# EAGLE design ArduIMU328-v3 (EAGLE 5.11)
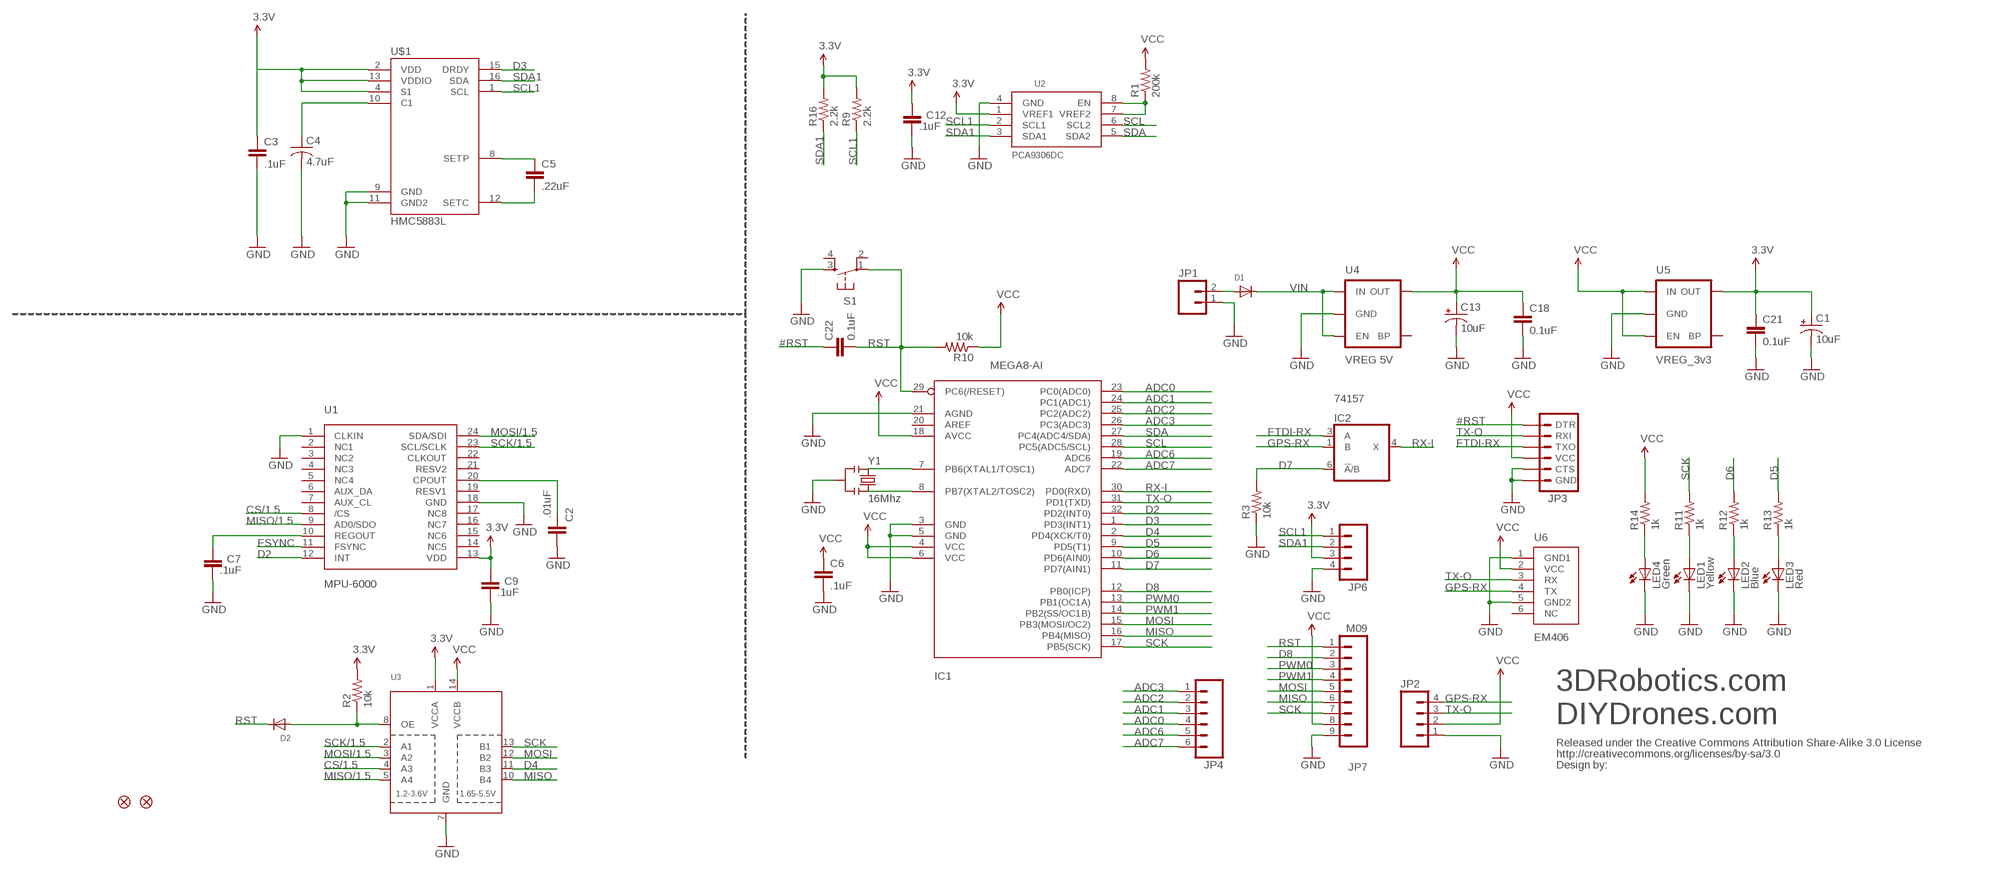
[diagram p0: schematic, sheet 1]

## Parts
C1  10uF  CAP_POL1206  [EIA3216]
C2  .01uF  C-EUC0402  [C0402]
C3  .1uF  CAP0402-CAP  [0402-CAP]
C4  4.7uF  C-USC1206  [C1206]
C5  .22uF  CAP0402-CAP  [0402-CAP]
C6  .1uF  CAP0402-CAP  [0402-CAP]
C7  .1uF  C-EUC0402  [C0402]
C9  .1uF  C-EUC0402  [C0402]
C12  .1uF  C-EUC0402  [C0402]
C13  10uF  CAP_POL1206  [EIA3216]
C18  0.1uF  CAP0402-CAP  [0402-CAP]
C21  0.1uF  CAP0402-CAP  [0402-CAP]
C22  0.1uF  CAP0402-CAP  [0402-CAP]
D1  DIODESOD-123  [SOD-123]
D2  DIODESOD-123  [SOD-123]
IC1  MEGA8-AI  [TQFP32-08]
IC2  74157  741G3157DBVR  [DBV_R-PDSO-G6]
JP1  M02PTH  [1X02]
JP2  M04PTH  [1X04]
JP3  ARDUINO_SERIAL_PROGRAMPTH  [1X06]
JP4  M06SIP  [1X06]
JP5  FIDUCIAL1X2  [FIDUCIAL-1X2]
JP6  M04PTH  [1X04]
JP7  M09  [1X09]
JP8  FIDUCIAL1X2  [FIDUCIAL-1X2]
LED1  Yellow  LED0603  [LED-0603]
LED2  Blue  LED0603  [LED-0603]
LED3  Red  LED0603  [LED-0603]
LED4  Green  LED0603  [LED-0603]
R1  200k  RESISTOR0402  [C0402]
R2  10k  RESISTOR0402-RES  [0402-RES]
R3  10k  RESISTOR0402-RES  [0402-RES]
R9  2.2k  RESISTOR0402  [C0402]
R10  10k  RESISTOR0402-RES  [0402-RES]
R11  1k  RESISTOR0402-RES  [0402-RES]
R12  1k  RESISTOR0402-RES  [0402-RES]
R13  1k  RESISTOR0402-RES  [0402-RES]
R14  1k  RESISTOR0402-RES  [0402-RES]
R16  2.2k  RESISTOR0402  [C0402]
S1  TAC_SWITCHSMD  [TACTILE_SWITCH_SMD]
U1  MPU-6000  MPU-3000  [QFN-24]
U2  PCA9306DC  [VSSOP8]
U3  TXB0104PWR  [TSSOP14]
U4  VREG 5V  V_REG_LDOSMD  [SOT23-5]
U5  VREG_3v3  V_REG_LDOSMD  [SOT23-5]
U6  EM406  [EM406]
U$1  HMC5883L  [LPCC16]
U$2  CREATIVE_COMMONS  [CREATIVE_COMMONS]
Y1  16Mhz  RESONATORSMD  [RESONATOR-SMD]

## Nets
3.3V: C1.A(+) C3.1 C9.2 C12.2 C21.1 JP6.3 R2.2 R9.2 R16.2 U1.13(VDD) U2.1(VREF1) U3.1(VCCA) U5.5(OUT) U$1.2(VDD) U$1.4(S1) U$1.13(VDDIO)
#RST: C22.1 JP3.1(DTR)
ADC0: IC1.23(PC0(ADC0)) JP4.4
ADC1: IC1.24(PC1(ADC1)) JP4.3
ADC2: IC1.25(PC2(ADC2)) JP4.2
ADC3: IC1.26(PC3(ADC3)) JP4.1
ADC6: IC1.19(ADC6) JP4.5
ADC7: IC1.22(ADC7) JP4.6
CS/1.5: U1.8(/CS) U3.4(A3)
D2: IC1.32(PD2(INT0)) U1.12(INT)
D3: IC1.1(PD3(INT1)) U$1.15(DRDY)
D4: IC1.2(PD4(XCK/T0)) U3.11(B3)
D5: IC1.9(PD5(T1)) R13.2
D6: IC1.10(PD6(AIN0)) R12.2
D7: IC1.11(PD7(AIN1)) IC2.6(!A!/B) R3.2
D8: IC1.12(PB0(ICP)) JP7.2
FSYNC: U1.11(FSYNC)
FTDI-RX: IC2.3(A) JP3.3(TXO)
GND: C1.C(-) C2.1 C3.2 C4.2 C6.2 C7.1 C9.1 C12.1 C13.C(-) C18.2 C21.2 IC1.3(GND) IC1.5(GND) IC1.21(AGND) JP1.1 JP2.1 JP3.5(CTS) JP3.6(GND) JP6.4 JP7.9 LED1.C LED2.C LED3.C LED4.C R3.1 S1.3 U1.1(CLKIN) U1.18(GND) U2.4(GND) U3.7(GND) U4.2(GND) U5.2(GND) U6.1(GND1) U6.5(GND2) U$1.9(GND) U$1.11(GND2) Y1.2
GPS-RX: IC2.1(B) JP2.4 U6.4(TX)
MISO: IC1.16(PB4(MISO)) JP7.6 U3.10(B4)
MISO/1.5: U1.9(AD0/SDO) U3.5(A4)
MOSI: IC1.15(PB3(MOSI/OC2)) JP7.5 U3.12(B2)
MOSI/1.5: U1.24(SDA/SDI) U3.3(A2)
N$1: R1.1 U2.7(VREF2) U2.8(EN)
N$2: C2.2 U1.20(CPOUT)
N$3: C7.2 U1.10(REGOUT)
N$4: C4.1 U$1.10(C1)
N$5: IC1.7(PB6(XTAL1/TOSC1)) Y1.1
N$6: C5.1 U$1.8(SETP)
N$7: IC1.8(PB7(XTAL2/TOSC2)) Y1.3
N$8: C5.2 U$1.12(SETC)
N$9: D2.A R2.1 U3.8(OE)
N$11: LED1.A R11.1
N$12: LED2.A R12.1
N$13: LED3.A R13.1
N$14: D1.A JP1.2
N$17: LED4.A R14.1
PWM0: IC1.13(PB1(OC1A)) JP7.3
PWM1: IC1.14(PB2(SS/OC1B)) JP7.4
RST: C22.2 D2.C IC1.29(PC6(/RESET)) JP7.1 R10.2 S1.1
RX-I: IC1.30(PD0(RXD)) IC2.4(X)
SCK: IC1.17(PB5(SCK)) JP7.7 R11.2 U3.13(B1)
SCK/1.5: U1.23(SCL/SCLK) U3.2(A1)
SCL: IC1.28(PC5(ADC5/SCL)) U2.6(SCL2)
SCL1: JP6.1 R9.1 U2.2(SCL1) U$1.1(SCL)
SDA: IC1.27(PC4(ADC4/SDA)) U2.5(SDA2)
SDA1: JP6.2 R16.1 U2.3(SDA1) U$1.16(SDA)
TX-O: IC1.31(PD1(TXD)) JP2.3 JP3.2(RXI) U6.3(RX)
VCC: C6.1 C13.A(+) C18.1 IC1.4(VCC) IC1.6(VCC) IC1.18(AVCC) JP2.2 JP3.4(VCC) JP7.8 R1.2 R10.1 R14.2 U3.14(VCCB) U4.5(OUT) U5.1(IN) U5.3(EN) U6.2(VCC)
VIN: D1.C U4.1(IN) U4.3(EN)
Unconnected: IC1.20(AREF) S1.2 S1.4 U1.2(NC1) U1.3(NC2) U1.4(NC3) U1.5(NC4) U1.6(AUX_DA) U1.7(AUX_CL) U1.14(NC5) U1.15(NC6) U1.16(NC7) U1.17(NC8) U1.19(RESV1) U1.21(RESV2) U1.22(CLKOUT) U4.4(BP) U5.4(BP) U6.6(NC)

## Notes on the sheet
- 3DRobotics.com
- DIYDrones.com

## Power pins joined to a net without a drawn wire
GND: IC2.2(GND)
VCC: IC2.5(VCC)

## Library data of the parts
C1 C13 = SparkFun:CAP_POL: Capacitor Polarized
C2 C7 C9 C12 = SmartPrj:C-EU: CAPACITOR, European symbol
C3 C5 C6 C18 C21 C22 = SparkFun:CAP: Capacitor
C4 = rcl:C-US: CAPACITOR, American symbol
D1 D2 = adafruit:DIODE: Diode
IC1 = atmel:MEGA8: MICROCONTROLLER 8 Kbytes FLASH, 1 kbytes SRAM, 512 bytes EEPROM, USART, 6-channel 10 bit ADC, 2-channel 8 bit ADC Pin compatible with Atmega48, ATMega88, ATMega168 Source: avr.lbr
IC2 = 74xx-little-de:74*1G3157: Single-Pole, Double-Throw Analog Switch Source: http://focus.ti.com/lit/ds/symlink/sn74lvc1g3157.pdf
JP1 = SparkFun:M02: Header 2
JP2 JP6 = SparkFun:M04: Header 4 Standard 4-pin 0.1" header. Use with straight break away headers (SKU : PRT-00116), right angle break away headers (PRT-00553), swiss pins (PRT-00743), machine pins (PRT-00117), and female headers (PRT-00115). Molex polarized connector foot print use with SKU : PRT-08231 with associated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
JP3 = SparkFun:ARDUINO_SERIAL_PROGRAM
JP4 = SparkFun:M06: Header 6 Standard 6-pin 0.1" header. Use with straight break away headers (SKU : PRT-00116), right angle break away headers (PRT-00553), swiss pins (PRT-00743), machine pins (PRT-00117), and female headers (PRT-00115). Molex polarized connector foot print use with SKU : PRT-08094 with associated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
JP5 JP8 = SparkFun:FIDUCIAL: Fiducial Alignment Points
JP7 = SparkFun:M09: Header 9 Standard 9-pin 0.1" header. Use with straight break away headers (SKU : PRT-00116), right angle break away headers (PRT-00553), swiss pins (PRT-00743), machine pins (PRT-00117), and female headers (PRT-00115).
LED1-LED4 = DIYdrones3:LED: LEDs
R1 R9 R16 = DIYdrones3:RESISTOR: Resistor
R2 R3 R10-R14 = SparkFun:RESISTOR: Resistor
S1 = DIYdrones3:TAC_SWITCH: Momentary Switch Button commonly used for reset or general input. Spark Fun Electronics SKU : COM-00097
U1 = 3DRobotics_Master_Library:MPU-3000: Invensense MPU-3000 Motion Processing Unit The MPU-30X0 Motion Processing Unit (MPU?) is the world?s first motion processing solution with integrated 6-axis sensor fusion for smart phone applications. The MPU-30X0 has an embedded 3- axis gyroscope and Digital Motion Processor? (DMP) hardware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; DATASHEET: http://invensense.com/mems/gyro/documents/PS-MPU-3000A-00_v2.6.pdf; LINK: http://www.invensense.com/mems/gyro/mpu3000.html; MFGPN: MPU-3000
U2 = DIYdrones_082610:PCA9306DC
U3 = adafruit:TXB0104PWR: 4-Bit Bi-Directional Level Shifter 1.2V-3.6V (VCCA) to 1.65V-5.5V (VCCB) bi-directional level shifter with auto direction sensing. Max data rate - VCCA 1.8V: 20Mbps (50ns), VCCA 3.3V: 100Mbps (10ns) Digikey: 296-21929-1-ND
U4 U5 = DIYdrones3:V_REG_LDO: Voltage Regulator LDO Standard 150mA LDO voltage regulator in SOT-23 layout. Micrel part MIC5205. BP (by-pass) pin is used to lower output noise with 470pF cap.
U6 = DIYdrones3:EM406: EM406 Connector Proven layout and schematic for EM406 connector. Spark Fun Electronics SKU : GPS-00579
U$1 = 3DRobotics:HMC5883L: Honeywell HMC5883L 3-axis digital compass IC Successor to the HMC5843.; DATASHEET: http://www.dsscircuits.com/images/datasheets/HMC5883L.pdf; LINK: http://parts.digikey.com/1/parts/2057013-ic-compass-3-axis-i2c-16lcc-smd-hmc5883l-tr.html; MFGPN: HMC5883L-TR
U$2 = SparkFun:CREATIVE_COMMONS
Y1 = DIYdrones3:RESONATOR: Resonator Small SMD resonator. This is the itty bitty 10/20MHz resonators with built in caps. CSTCE10M0G55 and CSTCE20M0V53. Footprint has been reviewed closely but hasn't been tested yet.

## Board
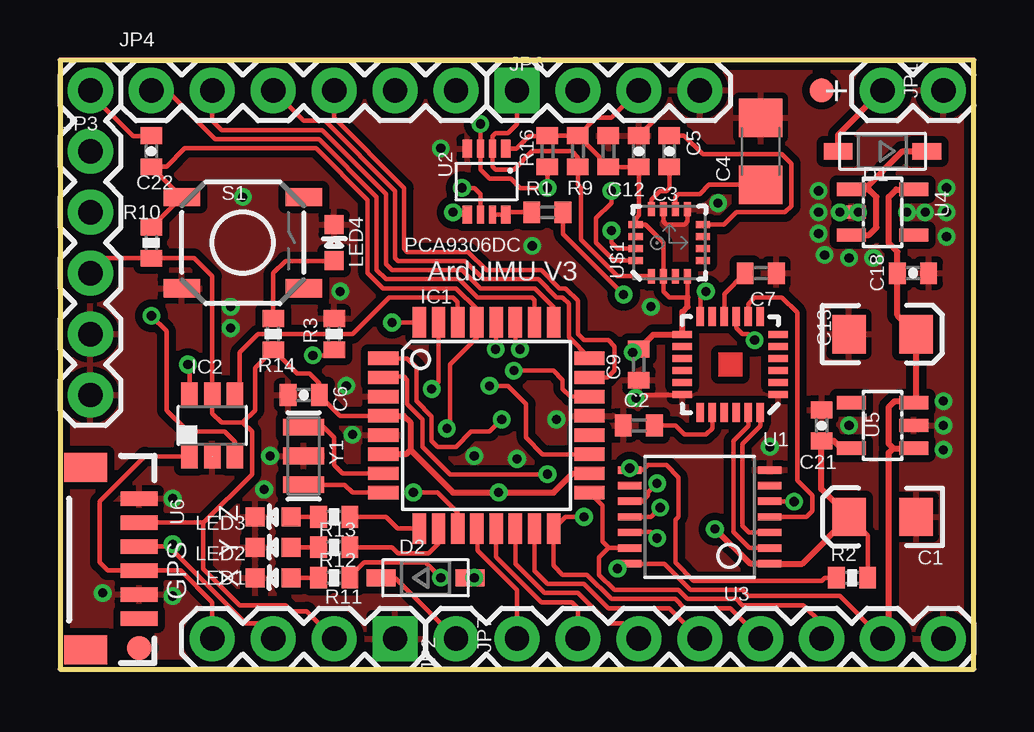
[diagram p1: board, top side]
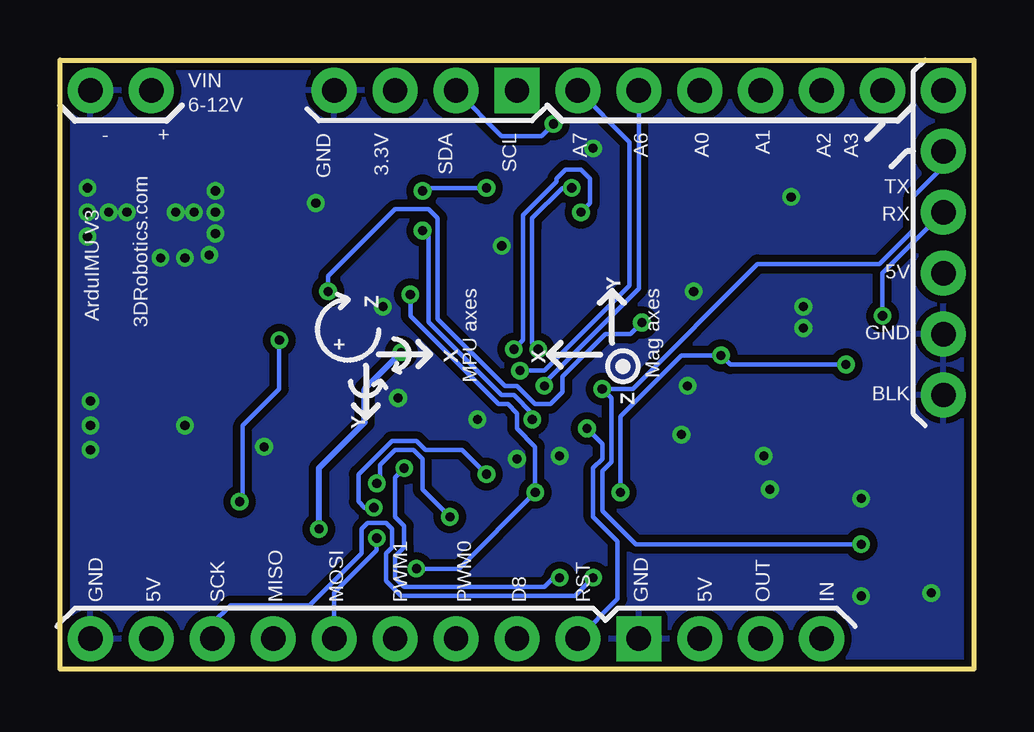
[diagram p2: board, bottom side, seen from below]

Size 38.1 x 25.4 mm. Coordinates in mm from the lower left corner, seen from the top.
Outline: 0,0 38.1,0 38.1,25.4 0,25.4 0,0
Copper layers (1*2+15*16): Top 0.035mm / dielectric 1.5mm / Route2 0.035mm / dielectric 0.15mm / Route15 0.035mm / dielectric 0.2mm / Bottom 0.035mm
Design rules "3DRobotics_4layers": minimum track width 7mil, minimum drill 15mil, track to track 7mil, track to pad 7mil, pad to pad 7mil, via to via 7mil, smd to smd 0mil, copper to edge 10mil, drill to drill 8mil, minimum pad ring 7mil, minimum via ring 7mil, stop-mask expansion 4mil, vias tented up to drill 25mil, thermal gap 10mil

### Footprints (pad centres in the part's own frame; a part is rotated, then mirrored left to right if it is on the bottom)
EIA3216 = smd 1.4 x 1.6: A 1.4,0; C -1.4,0
C0402 = smd 0.7 x 0.9: 1 -0.65,0; 2 0.65,0
0402-CAP = smd 0.7 x 0.9: 1 -0.65,0; 2 0.65,0
C1206 = smd 1.6 x 1.8: 1 -1.4,0; 2 1.4,0
SOD-123 = smd 1.2 x 0.7: A 1.85,0; C -1.85,0
TQFP32-08 = smd 1.27 x 0.559: 1 -4.293,2.8; 2 -4.293,2; 3 -4.293,1.2; 4 -4.293,0.4; 5 -4.293,-0.4; 6 -4.293,-1.2; 7 -4.293,-2; 8 -4.293,-2.8; 17 4.293,-2.8; 18 4.293,-2; 19 4.293,-1.2; 20 4.293,-0.4; 21 4.293,0.4; 22 4.293,1.2; 23 4.293,2; 24 4.293,2.8 | smd 0.559 x 1.27: 9 -2.8,-4.293; 10 -2,-4.293; 11 -1.2,-4.293; 12 -0.4,-4.293; 13 0.4,-4.293; 14 1.2,-4.293; 15 2,-4.293; 16 2.8,-4.293; 25 2.8,4.293; 26 2,4.293; 27 1.2,4.293; 28 0.4,4.293; 29 -0.4,4.293; 30 -1.2,4.293; 31 -2,4.293; 32 -2.8,4.293
DBV_R-PDSO-G6 = smd 0.69 x 0.99: 1 -0.95,-1.29; 2 0,-1.29; 3 0.95,-1.29; 4 0.95,1.3; 5 0,1.3; 6 -0.95,1.3
1X02 = drill 1.016 pad 1.88 round: 1 0,0; 2 2.54,0
1X04 = drill 1.016 pad 1.88 square: 1 0,0 | drill 1.016 pad 1.88 round: 2 2.54,0; 3 5.08,0; 4 7.62,0
1X06 = drill 1.016 pad 1.88 round: 1 0,0; 2 2.54,0; 3 5.08,0; 4 7.62,0; 5 10.16,0; 6 12.7,0
FIDUCIAL-1X2 = smd 1 x 1: 1 0,0
1X09 = drill 1.016 pad 1.88 round: 1 0,0; 2 2.54,0; 3 5.08,0; 4 7.62,0; 5 10.16,0; 6 12.7,0; 7 15.24,0; 8 17.78,0; 9 20.32,0
LED-0603 = smd 0.8 x 0.8: A 0,-0.75; C 0,0.75
0402-RES = smd 0.7 x 0.9: 1 -0.65,0; 2 0.65,0
TACTILE_SWITCH_SMD = smd 1.524 x 0.762: 1 -2.54,1.905; 2 2.54,1.905; 3 -2.54,-1.905; 4 2.54,-1.905
QFN-24 = smd 0.8 x 0.3: 1 -2,1.25; 2 -2,0.75; 3 -2,0.25; 4 -2,-0.25; 5 -2,-0.75; 6 -2,-1.25; 13 2,-1.25; 14 2,-0.75; 15 2,-0.25; 16 2,0.25; 17 2,0.75; 18 2,1.25 | smd 0.3 x 0.8: 7 -1.25,-2; 8 -0.75,-2; 9 -0.25,-2; 10 0.25,-2; 11 0.75,-2; 12 1.25,-2; 19 1.25,2; 20 0.75,2; 21 0.25,2; 22 -0.25,2; 23 -0.75,2; 24 -1.25,2
VSSOP8 = smd 0.75 x 0.4: 1 -1.375,0.8; 4 -1.375,-0.8; 5 1.375,-0.8; 8 1.375,0.8 | smd 0.75 x 0.3: 2 -1.375,0.25; 3 -1.375,-0.25; 6 1.375,-0.25; 7 1.375,0.25
TSSOP14 = smd 0.305 x 0.991: 1 -1.95,-2.918; 2 -1.3,-2.918; 3 -0.65,-2.918; 4 0,-2.918; 5 0.65,-2.918; 6 1.3,-2.918; 7 1.95,-2.918; 8 1.95,2.918; 9 1.3,2.918; 10 0.65,2.918; 11 0,2.918; 12 -0.65,2.918; 13 -1.3,2.918; 14 -1.95,2.918
SOT23-5 = smd 0.55 x 1.2: 1 -0.95,-1.3; 2 0,-1.3; 3 0.95,-1.3; 4 0.95,1.3; 5 -0.95,1.3
EM406 = smd 0.6 x 1.55: 1 0,0; 2 1,0; 3 2,0; 4 3,0; 5 4,0; 6 5,0 | smd 1.2 x 1.8: P$1 -1.3,-2.225; P$2 6.3,-2.225
LPCC16 = smd 0.6 x 0.3: 1 -1.4,0.75; 2 -1.4,0.25; 3 -1.4,-0.25; 4 -1.4,-0.75; 9 1.4,-0.75; 10 1.4,-0.25; 11 1.4,0.25; 12 1.4,0.75 | smd 0.3 x 0.6: 5 -0.75,-1.4; 6 -0.25,-1.4; 7 0.25,-1.4; 8 0.75,-1.4; 13 0.75,1.4; 14 0.25,1.4; 15 -0.25,1.4; 16 -0.75,1.4
RESONATOR-SMD = smd 0.7 x 1.7: 1 -1.2,0; 2 0,0; 3 1.2,0

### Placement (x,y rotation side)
C1  34.29,6.35 180 top
C2  24.13,10.16 0 top
C3  24.13,21.59 90 top
C4  29.21,21.59 90 top
C5  25.4,21.59 270 top
C6  10.16,11.43 180 top
C7  29.21,16.51 180 top
C9  24.13,12.7 90 top
C12  22.86,21.59 270 top
C13  34.29,13.97 0 top
C18  35.56,16.51 0 top
C21  31.75,10.16 90 top
C22  3.81,21.59 270 top
D1  34.29,21.59 180 top
D2  15.24,3.81 0 top
IC1  17.78,10.16 0 top
IC2  6.35,10.16 0 top
JP1  36.83,24.13 180 top
JP2  13.97,1.27 180 top
JP3  1.27,24.13 270 top
JP4  3.81,24.13 0 top
JP5  3.3,0.89 0 top
JP6  19.05,24.13 0 top
JP7  16.51,1.27 0 top
JP8  31.75,24.13 0 top
LED1  8.89,3.81 90 top
LED2  8.89,5.08 90 top
LED3  8.89,6.35 90 top
LED4  11.43,17.78 0 top
R1  20.32,19.05 0 top
R2  33.02,3.81 0 top
R3  11.43,13.97 270 top
R9  21.59,21.59 90 top
R10  3.81,17.78 90 top
R11  11.43,3.81 0 top
R12  11.43,5.08 0 top
R13  11.43,6.35 0 top
R14  8.89,13.97 270 top
R16  20.32,21.59 90 top
S1  7.62,17.78 0 top
U1  27.94,12.7 180 top
U2  17.78,20.32 270 top
U3  26.67,6.35 90 top
U4  34.29,19.05 270 top
U5  34.29,10.16 90 top
U6  3.3,7.11 270 top
U$1  25.4,17.78 90 top
U$2  not placed on the board
Y1  10.16,8.89 270 top

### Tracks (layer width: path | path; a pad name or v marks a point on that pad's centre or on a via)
3.3V  (via drill 0.38)
  Top 0.178: U$1.4 26.16,16.37 26.16,15.49 25.4,15.49 25.15,15.74 U$1.2 25.15,17.78 24.4,18.53 U$1.13 24,18.79 24.13,18.92 C3.1 C12.2 22.86,20.97 R9.2 | R9.2 21.61,22.24 22.35,22.99 22.99,22.99 JP6.3 | R9.2 R16.2 20.3,22.23 19.56,22.23 19.03,21.7 U2.1 | 31.73,9.51 C21.1 | R2.2 33.67,5.57 C1.A
  Top 0.254: 26.16,15.49 26.16,15.11 25.94,14.89 U1.13 24.73,13.95 C9.2 23.99,13.21 v23.88,13.21 | v27.3,5.84 28.78,4.4 U3.1 30.94,4.4 C1.A 31.73,7.5 31.73,9.51 | U5.5 32.57,9.21 32.26,9.53 31.77,9.53 C21.1
  Bottom 0.254: v27.3,5.84 27.3,8.38 25.4,10.29 25.4,11.68 v23.88,13.21
#RST
  Top 0.178: JP3.1 1.27,24 3.05,22.23 3.79,22.23 C22.1
ADC0
  Top 0.178: IC1.23 22.83,12.16 23.11,12.45 23.11,13.46 22.86,13.72 21.84,13.72 21.59,13.97 21.59,15.37 21.08,15.88 20.83,15.88 20.07,16.64 17.78,16.64 17.02,17.4 14.48,17.4 14.35,17.53 14.35,20.07 11.43,22.99 JP4.4
ADC1
  Top 0.178: IC1.24 22.07,12.98 21.21,13.84 21.21,15.24 20.95,15.49 20.7,15.49 19.94,16.26 17.65,16.26 16.89,17.02 14.1,17.02 13.97,17.14 13.97,19.94 11.05,22.86 10.16,22.86 JP4.3
ADC2
  Top 0.178: IC1.25 20.58,15.11 19.81,15.88 17.53,15.88 16.76,16.64 13.84,16.64 13.59,16.89 13.59,19.81 10.92,22.48 6.73,22.48 6.35,22.86 JP4.2
ADC3
  Top 0.178: IC1.26 19.78,15.4 19.68,15.49 17.4,15.49 16.64,16.26 13.59,16.26 13.21,16.64 13.21,19.68 10.79,22.1 6.48,22.1 4.45,24.13 JP4.1
ADC6  (via drill 0.38)
  Top 0.178: IC1.19 20.12,8.96 19.43,9.65 19.43,11.05 18.67,11.81 v17.91,11.81
  Bottom 0.178: JP4.5 13.97,15.88 17.91,11.94 v17.91,11.81
ADC7  (via drill 0.38)
  Top 0.178: IC1.22 21.28,11.36 20.95,11.68 20.95,12.06 20.57,12.45 v18.92,12.45
  Bottom 0.178: JP4.6 14.35,21.97 14.35,16 17.91,12.45 v18.92,12.45
CS/1.5
  Top 0.178: U1.8 28.69,15.23 28.96,15.49 30.1,15.49 30.73,14.86 30.73,7.87 31.37,7.24 31.37,6.6 31.11,6.35 U3.4
D2  (via drill 0.38)
  Top 0.178: IC1.32 v13.84,14.45 | U1.12 26.69,15.51 v26.92,15.75
  Bottom 0.178: v26.92,15.75 26.92,16.38 24.13,19.18 22.73,19.18 22.35,18.8 22.35,14.61 19.56,11.81 19.05,11.81 18.29,11.05 17.65,11.05 17.14,11.56 17.14,12.19 15.37,13.97 14.33,13.97 v13.84,14.45
D3  (via drill 0.38)
  Top 0.178: IC1.1 14.47,12.96 14.86,12.57 14.86,11.18 15.49,10.54 15.49,9.53 15.75,9.27 16.51,9.27 17.14,9.91 17.91,9.91 v18.41,10.41 | v22.99,18.29 22.99,17.78 23.24,17.53 U$1.15
  Bottom 0.178: v18.41,10.41 18.41,10.67 19.18,11.43 19.68,11.43 22.73,14.48 22.73,18.03 v22.99,18.29
D4  (via drill 0.38)
  Top 0.178: IC1.2 13.46,12.19 14.35,12.19 14.48,12.06 14.48,11.05 15.11,10.41 15.11,9.27 16.26,8.13 v20.32,8.13 | U3.11 24.64,6.35 v25.02,6.73
  Bottom 0.178: v25.02,6.73 25.4,6.73 25.65,6.99 25.65,8.13 24.26,9.53 23.24,9.53 22.86,9.14 21.34,9.14 v20.32,8.13
D5
  Top 0.178: IC1.9 14.07,5.87 13.59,6.35 R13.2
D6
  Top 0.178: IC1.10 15.78,5.24 15.37,4.83 14.1,4.83 13.84,5.08 R12.2
D7  (via drill 0.38)
  Top 0.178: IC2.6 5.4,12.63 v5.33,12.7 | v10.54,13.08 11.19,13.08 R3.2 | IC1.11 16.58,6.53 15.75,7.37 v14.73,7.37
  Bottom 0.178: v5.33,12.7 10.16,12.7 v10.54,13.08 12.19,13.08 14.73,10.54 v14.73,7.37
D8
  Top 0.178: JP7.2 19.05,3.3 17.4,4.95 17.4,5.85 IC1.12
FTDI-RX  (via drill 0.38)
  Top 0.178: IC2.3 7.3,9.46 6.86,9.91 5.33,9.91 4.45,10.79 4.45,14.1 v3.81,14.73
  Bottom 0.178: v3.81,14.73 3.81,16.51 JP3.3
GND  (via drill 0.38)
  Top 0.178: U$1.9 26.15,18.66 26.04,18.54 25.27,18.54 25.15,18.67 25.15,18.8 U$1.11 | 24.38,11.43 25.92,11.43 U1.18 | C3.2 24.14,22.24 25.02,23.11
  other vias: 12.19,9.78 27.43,19.43 29.59,9.27 20.7,10.41 24,11.3 11.94,11.81 8.76,8.89 11.68,15.75 15.88,21.72 4.7,7.11 4.7,3.05 7.11,14.22 7.11,15.11 7.62,19.68 19.68,17.65 24.64,15.11 17.27,8.89 19.05,8.76 8.51,7.49 1.78,3.17 31.62,19.05 31.62,18.16 31.62,19.94 36.96,20.07 36.96,19.05 36.96,18.03 32.89,17.14 36.07,19.05 35.31,19.05 32.51,19.05 33.27,19.05 31.88,17.27 33.91,17.14 32.89,10.16 36.83,10.16 36.83,11.18 36.83,9.14
  pour Bottom (isolate 0.305): -0.25,25.4 39.12,25.4 39.12,0 -0.25,0
  pour Top (isolate 0.305): -0.25,25.4 39.12,25.4 39.12,0 -0.25,0
GPS-RX
  Top 0.178: JP2.4 6.35,2.79 5.03,4.11 U6.4 1.98,4.11 1.65,4.45 1.65,6.99 3.54,8.87 IC2.1
MISO  (via drill 0.38)
  Top 0.178: JP7.6 27.94,2.54 26.04,2.54 25.65,2.92 22.99,2.92 21.97,3.94 20.95,3.94 20.57,4.32 IC1.16 21.06,6.35 v21.84,6.35 | U3.10 24.27,7 24.51,7.24 24.51,7.37 v24.89,7.75
  Bottom 0.178: v21.84,6.35 22.99,7.49 22.99,8.76 23.37,9.14 24.13,9.14 24.77,8.51 24.77,7.87 v24.89,7.75
MISO/1.5  (via drill 0.38)
  Top 0.178: U1.9 28.19,14.23 28.45,13.97 28.7,13.97 v28.96,13.72 | U3.5 30.59,7 v30.61,6.99
  Bottom 0.178: v28.96,13.72 28.96,11.68 30.48,10.16 30.48,7.11 v30.61,6.99
MOSI  (via drill 0.38)
  Top 0.178: JP7.5 25.4,2.54 22.86,2.54 21.84,3.56 20.32,3.56 19.78,4.1 IC1.15 | v24.89,5.46 24.64,5.71 23.77,5.71 U3.12
  Bottom 0.178: v24.89,5.46 24.89,4.95 26.67,3.17 JP7.5
MOSI/1.5
  Top 0.178: U3.3 28.72,5.7 28.45,5.97 28.45,9.4 29.19,10.14 U1.24
N$1
  Top 0.178: R1.1 18.68,19.05 U2.8 U2.7
N$2
  Top 0.178: U1.20 27.19,10.04 26.92,9.78 26.04,9.78 25.65,10.16 C2.2
N$3
  Top 0.178: U1.10 27.69,15.64 C7.2
N$4
  Top 0.178: U$1.10 25.65,19.68 25.78,19.81 26.67,19.81 27.05,20.19 C4.1
N$5
  Top 0.178: Y1.1 10.99,10.09 11.43,9.65 11.43,8.51 11.78,8.16 IC1.7
N$6
  Top 0.178: U$1.8 27.67,18.53 28.19,19.05 30.23,19.05 30.48,19.3 30.48,21.08 30.1,21.46 26.8,21.46 26.02,22.24 C5.1
N$7
  Top 0.178: IC1.8 12.2,7.36 11.87,7.69 Y1.3
N$8
  Top 0.178: U$1.12 24.65,19.57 25.02,19.94 25.27,19.94 25.4,20.07 C5.2
N$9  (via drill 0.38)
  Top 0.178: D2.A v17.27,3.81 | v23.75,8.38 U3.8 24.3,8.3 24.51,8.51 25.27,8.51 25.78,8 25.78,6.35 25.65,6.22 25.65,4.45 26.42,3.68 31.75,3.68 31.88,3.81 R2.1
  Bottom 0.178: v17.27,3.81 17.53,3.81 17.91,3.43 23.75,3.43 24.13,3.81 24.13,4.7 23.75,5.08 23.75,5.97 24.13,6.35 24.13,8 v23.75,8.38
N$11
  Top 0.178: LED1.A R11.1
N$12
  Top 0.178: LED2.A R12.1
N$13
  Top 0.178: LED3.A R13.1
N$14
  Top 0.254: D1.A 32.44,22.28 JP1.2
N$17
  Top 0.178: R14.1 8.89,16.51 9.4,17.02 11.42,17.02 LED4.A
PWM0
  Top 0.178: IC1.13 18.18,4.68 20.07,2.79 21.34,2.79 21.59,2.54 JP7.3
PWM1
  Top 0.178: JP7.4 23.5,1.91 22.86,1.91 21.59,3.17 20.19,3.17 18.98,4.39 IC1.14
RST  (via drill 0.38)
  Top 0.178: R10.2 3.83,18.43 S1.1 3.83,20.94 C22.2 3.83,20.95 4.45,20.95 5.21,21.72 10.67,21.72 12.83,19.56 12.83,16.51 13.46,15.88 16.51,15.88 17.38,15.01 IC1.29 17.38,13.82 16.26,12.7 16.26,10.16 v16.13,10.03 | D2.C 13.97,3.81 JP7.1
  Bottom 0.178: v16.13,10.03 15.49,9.4 15.49,8.76 15.88,8.38 15.88,6.35 14.86,5.33 14.86,2.92 JP7.1
RX-I
  Top 0.178: IC1.30 16.58,15.3 16.38,15.49 13.72,15.49 12.19,13.97 8.26,13.97 7.49,13.21 7.49,11.65 IC2.4
SCK  (via drill 0.38)
  Top 0.178: 22.89,5.05 U3.13 | 22.89,5.05 22.86,5.05 22.48,4.67 22.48,3.94 23.11,3.3 25.78,3.3 26.16,2.92 28.19,2.92 28.45,2.67 30.99,2.67 31.75,1.91 JP7.7 | 22.89,5.05 22.61,5.33 22.61,6.83 IC1.17 | R11.2 12.05,3.83 12.68,4.45 15.24,4.45 v15.88,3.81
  Bottom 0.178: JP7.7 31.75,1.91 30.99,2.67 27.69,2.67 25.53,4.83 25.53,5.84 25.27,6.1 24.51,6.1 24.26,5.84 24.26,5.08 24.51,4.83 24.51,3.68 23.88,3.05 16.64,3.05 v15.88,3.81
SCK/1.5
  Top 0.178: U1.23 28.69,10.15 28.07,9.53 28.07,5.71 28.73,5.05 U3.2
SCL  (via drill 0.38)
  Top 0.178: IC1.28 18.18,13.44 v18.16,13.34 | v16.76,20.07 17.27,20.07 17.53,19.81 U2.6
  Bottom 0.178: v18.16,13.34 18.41,13.59 18.41,18.41 18.41,18.8 17.14,20.07 v16.76,20.07
SCL1
  Top 0.178: JP6.1 19.05,22.73 18.67,22.35 18.16,22.35 18.03,22.22 U2.2 18.03,20.96 18.16,20.83 18.92,20.83 19.68,21.59 21.34,21.59 21.59,21.34 R9.1 21.59,20.19 21.72,20.07 21.72,17.91 23.24,16.38 U$1.1
SDA  (via drill 0.38)
  Top 0.178: U2.5 16.47,18.96 v16.38,19.05 | IC1.27 18.98,13.53 v19.18,13.34
  Bottom 0.178: v19.18,13.34 18.8,13.72 18.8,18.92 17.4,20.32 17.4,20.45 17.02,20.83 16.38,20.83 16,20.45 16,19.43 v16.38,19.05
SDA1  (via drill 0.38)
  Top 0.178: U$1.16 23.1,17.03 22.35,17.78 22.35,18.8 22.99,19.43 v22.99,19.94 | 17.53,20.82 17.53,20.83 | 17.53,20.82 U2.3 17.53,22.6 v17.53,22.73 | 17.53,20.82 17.91,20.45 18.8,20.45 19.18,20.07 v20.32,20.07 R16.1
  Bottom 0.178: v17.53,22.73 18.03,22.23 19.68,22.23 JP6.2 | v20.32,20.07 22.86,20.07 v22.99,19.94
TX-O  (via drill 0.38)
  Top 0.178: 4.54,5.11 U6.3 | 4.54,5.11 7.75,1.91 8.26,1.91 JP2.3 | 4.54,5.11 4.6,5.11 v4.7,5.21 | IC1.31 15.78,11.97 v15.49,11.68
  Bottom 0.178: v4.7,5.21 14.1,5.21 15.49,6.6 15.49,8.26 15.11,8.64 15.11,11.3 v15.49,11.68 14.22,11.68 9.02,16.89 3.94,16.89 2.54,18.29 2.54,19.68 1.27,20.95 JP3.2
VCC  (via drill 0.38)
  Top 0.178: JP7.8 32.51,3.05 28.7,3.05 28.45,3.3 26.29,3.3 25.19,4.4 U3.14 23.54,4.4 v23.24,4.19 | IC1.4 11.68,10.56 C6.1 10.81,11.92 10.41,12.32 9.89,12.32 R14.2 8.13,12.56 8.13,10.79 7.62,10.29 | 7.62,10.29 6.73,10.29 6.35,10.67 IC2.5 6.35,16.38 5.59,17.14 3.83,17.14 R10.1 1.89,17.13 JP3.4 | U6.2 5.99,6.11 | 5.99,6.11 8,8.13 8,9.91 7.62,10.29 | JP2.2 10.29,2.41 9.65,2.41 9.4,2.67 7.49,2.67 5.97,4.19 5.97,6.1 5.99,6.11 | R1.2 20.97,18.15 v23.5,15.62
  Top 0.254: U4.5 34.86,20 34.54,19.68 34.54,17.77 34.91,17.4 C18.1 34.91,14.75 C13.A | 34.74,9.21 34.73,9.21 34.54,9.4 34.54,10.92 34.8,11.18 35.52,11.18 U5.3 35.69,11.21 C13.A | 34.74,9.21 U5.1 | JP7.8 34.54,1.52 34.54,9.02 34.74,9.21 | IC1.4 14.33,10.56 14.61,10.29 14.61,9.14 | IC1.6 14.42,8.96 14.61,9.14 | IC1.18 21.37,8.16 20.57,7.37 v18.29,7.37 16.38,7.37 14.61,9.14 | C13.A
  Bottom 0.178: v23.5,15.62 23.5,14.73 19.81,11.05 19.43,11.05 19.05,10.67 19.05,10.03 18.29,9.27 v18.29,7.37 21.46,4.19 v23.24,4.19
VIN
  Top 0.254: 33.53,20 33.72,20 34.04,19.68 34.04,18.41 33.72,18.1 U4.3 | 33.53,20 U4.1 | D1.C 35.12,21.59 33.53,20

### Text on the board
tPlace: + | ArduIMU V3 | Z | GPS | Y | X
bPlace: VIN | 6-12V | + | - | SCL | SDA | 3.3V | GND | A3 | A2 | A1 | A0 | A6 | A7 | 3DRobotics.com | TX | RX | ArduIMU V3 | 5V | Mag axes | Y | MPU axes | Z | GND | X | X | + | BLK | Z | Y | IN | OUT | 5V | GND | RST | D8 | PWM0 | PWM1 | MOSI | MISO | SCK | 5V | GND
tValues: Jordi Muñoz/3D Robotics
